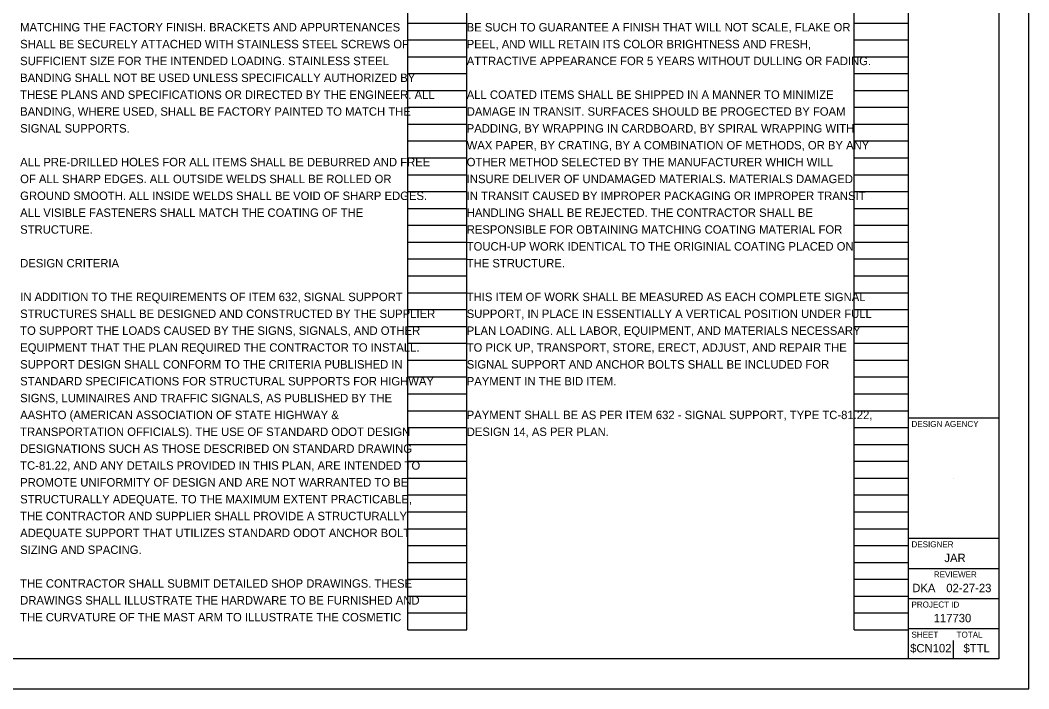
# Model space of a CAD drawing. Extents: x 0 to 34, y 0 to 22.
# Drawn here: x 17.24 to 34, y 0 to 11.11 of the extents above; entities that cross this region are included whole.
import ezdxf

# ---------------------------------------------------------------- set-up
doc = ezdxf.new("R2010")
doc.units = 0
for name, color, linetype in [('SH_Border', 7, 'Continuous'), ('SH_Cut_Line', 7, 'Continuous'), ('SH_Data', 7, 'Continuous'), ('SH_Text', 7, 'Continuous')]:
    doc.layers.add(name, color=color, linetype=linetype)

msp = doc.modelspace()

# ---------------------------------------------------------------- linework, layer by layer
at = {"layer": 'SH_Border'}
for p, q in [((32, 0.5), (32, 21.5)), ((32, 4.5), (33.5, 4.5)), ((32, 2.5), (33.5, 2.5)), ((32, 2), (33.5, 2)), ((32, 1.5), (33.5, 1.5)), ((32, 1), (33.5, 1))]:
    msp.add_line(p, q, dxfattribs=at)
msp.add_lwpolyline([(1.5, 21.5), (33.5, 21.5), (33.5, 0.5), (1.5, 0.5)], close=True, dxfattribs=at)
at = {"layer": 'SH_Cut_Line'}
msp.add_lwpolyline([(0, 0), (34, 0), (34, 22), (0, 22)], close=True, dxfattribs=at)
at = {"layer": 'SH_Data'}
for p, q in [((23.68, 0.98), (23.68, 21.14)), ((24.66, 0.98), (24.66, 21.14)), ((31.1, 0.98), (31.1, 21.14)), ((32, 0.98), (32, 21.14)), ((23.68, 11.06), (24.66, 11.06)), ((31.1, 11.06), (32, 11.06)), ((23.68, 10.78), (24.66, 10.78)), ((31.1, 10.78), (32, 10.78)), ((23.68, 10.5), (24.66, 10.5)), ((31.1, 10.5), (32, 10.5)), ((23.68, 10.22), (24.66, 10.22)), ((31.1, 10.22), (32, 10.22)), ((23.68, 9.94), (24.66, 9.94)), ((31.1, 9.94), (32, 9.94)), ((23.68, 9.66), (24.66, 9.66)), ((31.1, 9.66), (32, 9.66)), ((23.68, 9.38), (24.66, 9.38)), ((31.1, 9.38), (32, 9.38)), ((23.68, 9.1), (24.66, 9.1)), ((31.1, 9.1), (32, 9.1)), ((23.68, 8.82), (24.66, 8.82)), ((31.1, 8.82), (32, 8.82)), ((23.68, 8.54), (24.66, 8.54)), ((31.1, 8.54), (32, 8.54)), ((23.68, 8.26), (24.66, 8.26)), ((31.1, 8.26), (32, 8.26)), ((23.68, 7.98), (24.66, 7.98)), ((31.1, 7.98), (32, 7.98)), ((23.68, 7.7), (24.66, 7.7)), ((31.1, 7.7), (32, 7.7)), ((23.68, 7.42), (24.66, 7.42)), ((31.1, 7.42), (32, 7.42)), ((23.68, 7.14), (24.66, 7.14)), ((31.1, 7.14), (32, 7.14)), ((23.68, 6.86), (24.66, 6.86)), ((31.1, 6.86), (32, 6.86)), ((23.68, 6.58), (24.66, 6.58)), ((31.1, 6.58), (32, 6.58)), ((23.68, 6.3), (24.66, 6.3)), ((31.1, 6.3), (32, 6.3)), ((23.68, 6.02), (24.66, 6.02)), ((31.1, 6.02), (32, 6.02)), ((23.68, 5.74), (24.66, 5.74)), ((31.1, 5.74), (32, 5.74)), ((23.68, 5.46), (24.66, 5.46)), ((31.1, 5.46), (32, 5.46)), ((23.68, 5.18), (24.66, 5.18)), ((31.1, 5.18), (32, 5.18)), ((23.68, 4.9), (24.66, 4.9)), ((31.1, 4.9), (32, 4.9)), ((23.68, 4.62), (24.66, 4.62)), ((31.1, 4.62), (32, 4.62)), ((23.68, 4.34), (24.66, 4.34)), ((31.1, 4.34), (32, 4.34)), ((23.68, 4.06), (24.66, 4.06)), ((31.1, 4.06), (32, 4.06)), ((23.68, 3.78), (24.66, 3.78)), ((31.1, 3.78), (32, 3.78)), ((23.68, 3.5), (24.66, 3.5)), ((31.1, 3.5), (32, 3.5)), ((32.75, 3.5), (32.75, 3.5)), ((23.68, 3.22), (24.66, 3.22)), ((31.1, 3.22), (32, 3.22)), ((23.68, 2.94), (24.66, 2.94)), ((31.1, 2.94), (32, 2.94)), ((23.68, 2.66), (24.66, 2.66)), ((31.1, 2.66), (32, 2.66)), ((23.68, 2.38), (24.66, 2.38)), ((31.1, 2.38), (32, 2.38)), ((23.68, 2.1), (24.66, 2.1)), ((31.1, 2.1), (32, 2.1)), ((23.68, 1.82), (24.66, 1.82)), ((31.1, 1.82), (32, 1.82)), ((23.68, 1.54), (24.66, 1.54)), ((31.1, 1.54), (32, 1.54)), ((23.68, 1.26), (24.66, 1.26)), ((31.1, 1.26), (32, 1.26)), ((23.68, 0.98), (24.66, 0.98)), ((31.1, 0.98), (32, 0.98)), ((32.375, 0.675), (32.375, 0.675)), ((32.75, 0.5), (32.75, 0.8))]:
    msp.add_line(p, q, dxfattribs=at)

# ---------------------------------------------------------------- texts
for s, height, p in [('DESIGN AGENCY', 0.1, (32.05, 4.35)), ('DESIGNER', 0.1, (32.05, 2.35)), ('JAR', 0.14, (32.597, 2.105)), ('REVIEWER', 0.1, (32.422, 1.85)), ('DKA', 0.14, (32.063, 1.605)), ('02-27-23', 0.14, (32.629, 1.605)), ('PROJECT ID', 0.1, (32.05, 1.35)), ('117730', 0.14, (32.419, 1.105)), ('SHEET', 0.1, (32.05, 0.85)), ('TOTAL', 0.1, (32.8, 0.85)), ('$CN102', 0.14, (32.028, 0.605)), ('$TTL', 0.14, (32.915, 0.605))]:
    msp.add_text(s, height=height, dxfattribs=at).set_placement(p)
at = {"layer": 'SH_Text'}
for s, p in [('MATCHING THE FACTORY FINISH. BRACKETS AND APPURTENANCES ', (17.24, 10.92)), ('BE SUCH TO GUARANTEE A FINISH THAT WILL NOT SCALE, FLAKE OR ', (24.66, 10.92)), ('SHALL BE SECURELY ATTACHED WITH STAINLESS STEEL SCREWS OF ', (17.24, 10.64)), ('PEEL, AND WILL RETAIN ITS COLOR BRIGHTNESS AND FRESH, ', (24.66, 10.64)), ('SUFFICIENT SIZE FOR THE INTENDED LOADING. STAINLESS STEEL ', (17.24, 10.36)), ('ATTRACTIVE APPEARANCE FOR 5 YEARS WITHOUT DULLING OR FADING.', (24.66, 10.36)), ('BANDING SHALL NOT BE USED UNLESS SPECIFICALLY AUTHORIZED BY ', (17.24, 10.08)), ('THESE PLANS AND SPECIFICATIONS OR DIRECTED BY THE ENGINEER. ALL ', (17.24, 9.8)), ('ALL COATED ITEMS SHALL BE SHIPPED IN A MANNER TO MINIMIZE ', (24.66, 9.8)), ('BANDING, WHERE USED, SHALL BE FACTORY PAINTED TO MATCH THE ', (17.24, 9.52)), ('DAMAGE IN TRANSIT. SURFACES SHOULD BE PROGECTED BY FOAM ', (24.66, 9.52)), ('SIGNAL SUPPORTS.', (17.24, 9.24)), ('PADDING, BY WRAPPING IN CARDBOARD, BY SPIRAL WRAPPING WITH ', (24.66, 9.24)), ('WAX PAPER, BY CRATING, BY A COMBINATION OF METHODS, OR BY ANY ', (24.66, 8.96)), ('ALL PRE-DRILLED HOLES FOR ALL ITEMS SHALL BE DEBURRED AND FREE ', (17.24, 8.68)), ('OTHER METHOD SELECTED BY THE MANUFACTURER WHICH WILL ', (24.66, 8.68)), ('OF ALL SHARP EDGES. ALL OUTSIDE WELDS SHALL BE ROLLED OR ', (17.24, 8.4)), ('INSURE DELIVER OF UNDAMAGED MATERIALS. MATERIALS DAMAGED ', (24.66, 8.4)), ('GROUND SMOOTH. ALL INSIDE WELDS SHALL BE VOID OF SHARP EDGES. ', (17.24, 8.12)), ('IN TRANSIT CAUSED BY IMPROPER PACKAGING OR IMPROPER TRANSIT ', (24.66, 8.12)), ('ALL VISIBLE FASTENERS SHALL MATCH THE COATING OF THE ', (17.24, 7.84)), ('HANDLING SHALL BE REJECTED. THE CONTRACTOR SHALL BE ', (24.66, 7.84)), ('STRUCTURE.', (17.24, 7.56)), ('RESPONSIBLE FOR OBTAINING MATCHING COATING MATERIAL FOR ', (24.66, 7.56)), ('TOUCH-UP WORK IDENTICAL TO THE ORIGINIAL COATING PLACED ON ', (24.66, 7.28)), ('DESIGN CRITERIA', (17.24, 7)), ('THE STRUCTURE.', (24.66, 7)), ('IN ADDITION TO THE REQUIREMENTS OF ITEM 632, SIGNAL SUPPORT ', (17.24, 6.44)), ('THIS ITEM OF WORK SHALL BE MEASURED AS EACH COMPLETE SIGNAL ', (24.66, 6.44)), ('STRUCTURES SHALL BE DESIGNED AND CONSTRUCTED BY THE SUPPLIER ', (17.24, 6.16)), ('SUPPORT, IN PLACE IN ESSENTIALLY A VERTICAL POSITION UNDER FULL ', (24.66, 6.16)), ('TO SUPPORT THE LOADS CAUSED BY THE SIGNS, SIGNALS, AND OTHER ', (17.24, 5.88)), ('PLAN LOADING. ALL LABOR, EQUIPMENT, AND MATERIALS NECESSARY ', (24.66, 5.88)), ('EQUIPMENT THAT THE PLAN REQUIRED THE CONTRACTOR TO INSTALL. ', (17.24, 5.6)), ('TO PICK UP, TRANSPORT, STORE, ERECT, ADJUST, AND REPAIR THE ', (24.66, 5.6)), ('SUPPORT DESIGN SHALL CONFORM TO THE CRITERIA PUBLISHED IN ', (17.24, 5.32)), ('SIGNAL SUPPORT AND ANCHOR BOLTS SHALL BE INCLUDED FOR ', (24.66, 5.32)), ('STANDARD SPECIFICATIONS FOR STRUCTURAL SUPPORTS FOR HIGHWAY ', (17.24, 5.04)), ('PAYMENT IN THE BID ITEM.', (24.66, 5.04)), ('SIGNS, LUMINAIRES AND TRAFFIC SIGNALS, AS PUBLISHED BY THE ', (17.24, 4.76)), ('AASHTO (AMERICAN ASSOCIATION OF STATE HIGHWAY & ', (17.24, 4.48)), ('PAYMENT SHALL BE AS PER ITEM 632 - SIGNAL SUPPORT, TYPE TC-81.22, ', (24.66, 4.48)), ('TRANSPORTATION OFFICIALS). THE USE OF STANDARD ODOT DESIGN ', (17.24, 4.2)), ('DESIGN 14, AS PER PLAN.', (24.66, 4.2)), ('DESIGNATIONS SUCH AS THOSE DESCRIBED ON STANDARD DRAWING ', (17.24, 3.92)), ('TC-81.22, AND ANY DETAILS PROVIDED IN THIS PLAN, ARE INTENDED TO ', (17.24, 3.64)), ('PROMOTE UNIFORMITY OF DESIGN AND ARE NOT WARRANTED TO BE ', (17.24, 3.36)), ('STRUCTURALLY ADEQUATE. TO THE MAXIMUM EXTENT PRACTICABLE, ', (17.24, 3.08)), ('THE CONTRACTOR AND SUPPLIER SHALL PROVIDE A STRUCTURALLY ', (17.24, 2.8)), ('ADEQUATE SUPPORT THAT UTILIZES STANDARD ODOT ANCHOR BOLT ', (17.24, 2.52)), ('SIZING AND SPACING.', (17.24, 2.24)), ('THE CONTRACTOR SHALL SUBMIT DETAILED SHOP DRAWINGS. THESE ', (17.24, 1.68)), ('DRAWINGS SHALL ILLUSTRATE THE HARDWARE TO BE FURNISHED AND ', (17.24, 1.4)), ('THE CURVATURE OF THE MAST ARM TO ILLUSTRATE THE COSMETIC ', (17.24, 1.12))]:
    msp.add_text(s, height=0.14, dxfattribs=at).set_placement(p)

doc.saveas('drawing.dxf')
